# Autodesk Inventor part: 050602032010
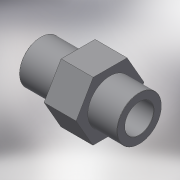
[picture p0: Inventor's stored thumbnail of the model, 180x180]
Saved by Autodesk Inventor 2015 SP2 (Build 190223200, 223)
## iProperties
Created: 2017-10
Part Number: 050602032010
Material: Generic
Description: PLASSON NIPPLE THR-CEM PVC 32(25)1"
Document SubType Name: Modeling
Designer: KIM
Mass: 25.6589 g
Surface Area: 114.425 cm^2
Volume: 25.6589 cm^3
Density: 1 g/cm^3
Appearance: Default
Author: KIM
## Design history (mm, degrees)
derived "050602.ipt"
feature "Solid1::050602.ipt"
tag "TaggingFeature1"
body "Solid1"
other parameters: "d0" = 55, "d2" = 36, "d13" = 0, "d14" = 0.25, "d17" = 22, "d18" = 22.8, "d19" = 32, "d20" = 25, "d21" = 33.249, "d22" = 19, "d23" = 23.75, "d24" = 22.5, "d25" = 19, "d26" = -22, "d_" = 25, "R_" = 33.249, "C_" = 36, "B_" = 12, "L_" = 22, "lt_" = 19, "H_" = 55, "D_" = 32, "l_" = 19
